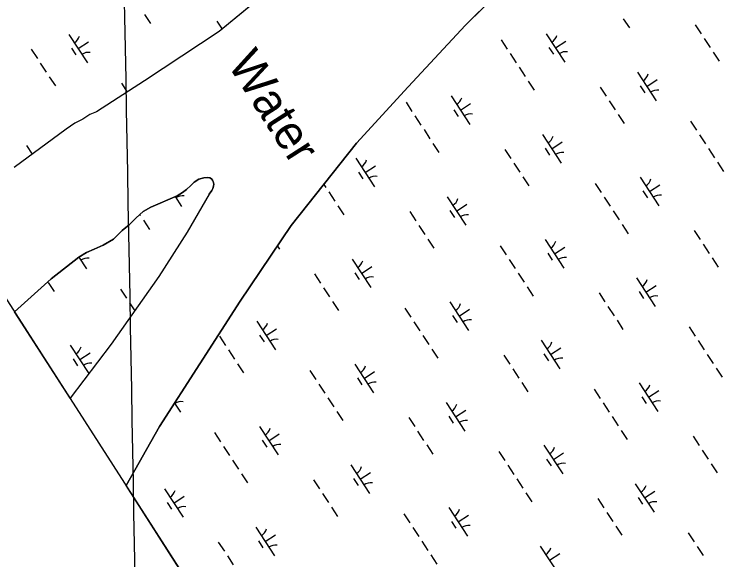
# Model space of a CAD drawing. Extents: x 3945642 to 3966284, y 206476 to 228921.
# Drawn here: x 3951439 to 3952485, y 218632 to 219430 of the extents above; entities that cross this region are included whole.
import ezdxf

# ---------------------------------------------------------------- set-up
doc = ezdxf.new("R2010")
doc.units = 0
for name, color, linetype in [('V-GRID-FRAM', 7, 'Continuous'), ('V-GRID-MAJR', 7, 'Continuous'), ('V-RIVR-IDEN', 7, 'Continuous'), ('V-TOPO-SHOR', 7, 'Continuous'), ('V-WETL-SWMP', 7, 'Continuous')]:
    doc.layers.add(name, color=color, linetype=linetype)

msp = doc.modelspace()

# ---------------------------------------------------------------- linework, layer by layer
at = {"layer": 'V-GRID-FRAM'}
msp.add_lwpolyline([(3956475, 226502.1), (3964764.2, 213849), (3957669.1, 209282.6), (3949512, 222000.5), (3956475, 226502.1)], dxfattribs=at)
at = {"layer": 'V-GRID-MAJR'}
msp.add_spline([(3951631.4, 217770), (3951621.8, 218291.8), (3951515.4, 224098.9)], degree=3, dxfattribs=at)
at = {"layer": 'V-TOPO-SHOR'}
for points in [[(3952516.2, 219647.7), (3952413.8, 219612.1), (3952398.5, 219606.6), (3952388.4, 219602.3), (3952380.9, 219598.4), (3952373.2, 219594.9), (3952364, 219592), (3952354.9, 219589.5), (3952248.7, 219535.6), (3952209.6, 219512.6), (3952194.3, 219504), (3952183.8, 219494.8), (3952174.7, 219486.4), (3952166.1, 219479.3), (3952152.1, 219466.9), (3952098.8, 219414.1), (3952015.1, 219324), (3951939.5, 219241.4), (3951844.2, 219121.1), (3951769.5, 219010.5), (3951651.5, 218826.9), (3951602.7, 218740.9)], [(3951841.5, 219489.7), (3951738.6, 219404.8), (3951629.8, 219332.5), (3951559.3, 219287.4), (3951549.8, 219283.3), (3951539.6, 219276.8), (3951527.8, 219270.7), (3951515.1, 219262.1), (3951438.9, 219205.9)], [(3951724, 219167), (3951728.2, 219172.4), (3951729.5, 219175.1), (3951730.4, 219178.5), (3951730.8, 219181.8), (3951730.1, 219185.5), (3951729.3, 219187.2), (3951727.5, 219189.3), (3951725.3, 219190.6), (3951721.6, 219191.4), (3951716.4, 219190.8), (3951709.1, 219188.7), (3951702.3, 219184.4), (3951697.2, 219179.7), (3951691.2, 219173.8), (3951685.2, 219169.3), (3951677.3, 219164.7), (3951639.1, 219148.1), (3951627.7, 219141.4), (3951617.7, 219132.5), (3951607.2, 219122.2), (3951597.2, 219113.6), (3951584.1, 219101.3), (3951569, 219092.2), (3951556.1, 219086.7), (3951544.8, 219081.4), (3951533.8, 219074.6), (3951493.4, 219043.1), (3951439.7, 218995)], [(3951724, 219167), (3951692.2, 219111.1), (3951650.5, 219046.4), (3951581, 218947.6), (3951520.8, 218868.5)]]:
    msp.add_lwpolyline(points, dxfattribs=at)
at = {"layer": 'V-WETL-SWMP'}
for p, q in [((3951841.5, 219489.7), (3951738.6, 219404.8)), ((3952098.8, 219414.1), (3952152.1, 219466.9)), ((3951629.6, 219429.9), (3951638.4, 219416.5)), ((3952329.7, 219423.5), (3952338.5, 219410.1)), ((3951735.3, 219420.2), (3951743, 219408.5)), ((3952015.1, 219324), (3952098.8, 219414.1)), ((3952434.9, 219414.8), (3952443.7, 219401.4)), ((3951738.6, 219404.8), (3951629.8, 219332.5)), ((3952216.9, 219401.7), (3952244.3, 219359.9)), ((3951518.9, 219400.7), (3951546.3, 219358.9)), ((3952151.1, 219392.6), (3952159.9, 219379.2)), ((3952230.6, 219380.8), (3952245.6, 219390.7)), ((3952448.1, 219394.7), (3952456.8, 219381.4)), ((3951522.8, 219380.6), (3951529.4, 219370.6)), ((3951532.6, 219379.8), (3951547.6, 219389.7)), ((3952220.8, 219381.6), (3952227.4, 219371.6)), ((3951464.2, 219378.9), (3951473, 219365.5)), ((3952164.2, 219372.5), (3952173, 219359.1)), ((3952461.2, 219374.7), (3952470, 219361.3)), ((3951477.3, 219358.8), (3951486.1, 219345.4)), ((3952177.4, 219352.5), (3952186.2, 219339.1)), ((3951490.5, 219338.7), (3951499.3, 219325.4)), ((3952350.5, 219345.5), (3952377.9, 219303.7)), ((3951629.8, 219332.5), (3951559.3, 219287.4)), ((3951596.2, 219329.1), (3951604.5, 219316.3)), ((3952190.6, 219332.4), (3952199.3, 219319)), ((3952364.2, 219324.6), (3952379.2, 219334.5)), ((3951939.5, 219241.4), (3952015.1, 219324)), ((3952295.8, 219323.7), (3952304.6, 219310.3)), ((3952354.4, 219325.4), (3952361, 219315.3)), ((3952077.8, 219310.6), (3952105.2, 219268.8)), ((3952012, 219301.5), (3952020.7, 219288.1)), ((3952091.5, 219289.7), (3952106.5, 219299.5)), ((3952308.9, 219303.6), (3952317.7, 219290.2)), ((3951559.3, 219287.4), (3951549.8, 219283.3)), ((3952081.7, 219290.5), (3952088.3, 219280.4)), ((3951539.6, 219276.8), (3951527.8, 219270.6)), ((3951549.8, 219283.3), (3951539.6, 219276.8)), ((3952025.1, 219281.4), (3952033.9, 219268)), ((3952322.1, 219283.5), (3952330.9, 219270.1)), ((3951527.8, 219270.6), (3951515.1, 219262.1)), ((3952427.8, 219273.8), (3952436.5, 219260.5)), ((3951515.1, 219262.1), (3951438.9, 219205.9)), ((3952038.3, 219261.3), (3952047, 219247.9)), ((3952211.3, 219254.4), (3952238.7, 219212.5)), ((3952440.9, 219253.8), (3952449.7, 219240.4)), ((3951457, 219237.9), (3951465.3, 219225.3)), ((3951844.2, 219121.1), (3951939.5, 219241.4)), ((3952051.4, 219241.2), (3952060.2, 219227.8)), ((3952215.3, 219234.2), (3952221.9, 219224.2)), ((3952225, 219233.4), (3952240.1, 219243.3)), ((3952454.1, 219233.7), (3952462.8, 219220.3)), ((3952156.6, 219232.5), (3952165.4, 219219.1)), ((3951938.6, 219219.4), (3951966, 219177.6)), ((3952467.2, 219213.6), (3952476, 219200.2)), ((3951952.3, 219198.5), (3951967.4, 219208.4)), ((3952169.8, 219212.4), (3952178.6, 219199.1)), ((3951942.6, 219199.3), (3951949.1, 219189.3)), ((3952182.9, 219192.4), (3952191.7, 219179)), ((3952354.4, 219191.8), (3952381.8, 219150)), ((3951697.2, 219179.7), (3951702.3, 219184.4)), ((3951702.3, 219184.4), (3951709.1, 219188.7)), ((3951709.1, 219188.7), (3951716.4, 219190.8)), ((3951716.4, 219190.8), (3951721.6, 219191.4)), ((3951721.6, 219191.4), (3951725.3, 219190.6)), ((3951725.3, 219190.6), (3951727.5, 219189.3)), ((3951727.5, 219189.3), (3951729.3, 219187.2)), ((3951729.3, 219187.2), (3951730.1, 219185.5)), ((3951730.1, 219185.5), (3951730.8, 219181.8)), ((3951730.8, 219181.8), (3951730.4, 219178.5)), ((3951891.8, 219181.3), (3951894.7, 219176.8)), ((3952288.6, 219182.7), (3952297.4, 219169.3)), ((3951685.2, 219169.3), (3951691.2, 219173.8)), ((3951691.2, 219173.8), (3951697.2, 219179.7)), ((3951728.2, 219172.4), (3951724, 219167)), ((3951729.5, 219175.1), (3951728.2, 219172.4)), ((3951730.4, 219178.5), (3951729.5, 219175.1)), ((3952358.4, 219171.7), (3952364.9, 219161.7)), ((3952368.1, 219170.9), (3952383.2, 219180.8)), ((3951639.1, 219148.1), (3951677.3, 219164.7)), ((3951674.3, 219163.4), (3951683.8, 219149)), ((3951677.3, 219164.7), (3951685.2, 219169.3)), ((3951724, 219167), (3951692.2, 219111.1)), ((3951899.1, 219170.2), (3951907.9, 219156.8)), ((3952072.2, 219163.2), (3952099.6, 219121.4)), ((3952301.8, 219162.6), (3952310.5, 219149.2)), ((3951912.3, 219150.1), (3951921, 219136.7)), ((3952085.9, 219142.3), (3952101, 219152.2)), ((3951617.7, 219132.5), (3951627.7, 219141.4)), ((3951627.7, 219141.4), (3951639.1, 219148.1)), ((3952017.5, 219141.4), (3952026.3, 219128)), ((3952076.2, 219143.1), (3952082.7, 219133)), ((3952314.9, 219142.5), (3952323.7, 219129.2)), ((3951607.2, 219122.2), (3951617.7, 219132.5)), ((3951622.7, 219136.9), (3951623.6, 219135.5)), ((3951597.2, 219113.6), (3951607.2, 219122.2)), ((3951628, 219128.8), (3951636.8, 219115.4)), ((3951769.5, 219010.5), (3951844.2, 219121.1)), ((3952030.7, 219121.3), (3952039.4, 219107.9)), ((3952328.1, 219122.5), (3952336.8, 219109.1)), ((3951584.1, 219101.3), (3951597.2, 219113.6)), ((3951692.2, 219111.1), (3951650.5, 219046.4)), ((3952433.3, 219113.7), (3952442.1, 219100.4)), ((3951569, 219092.2), (3951584.1, 219101.3)), ((3952043.8, 219101.2), (3952052.6, 219087.8)), ((3952215.3, 219100.7), (3952242.7, 219058.8)), ((3951556.1, 219086.7), (3951569, 219092.2)), ((3951823.9, 219091), (3951826.9, 219086.5)), ((3952149.5, 219091.5), (3952158.2, 219078.2)), ((3952229, 219079.7), (3952244, 219089.6)), ((3952446.5, 219093.7), (3952455.2, 219080.3)), ((3951533.8, 219074.6), (3951544.8, 219081.4)), ((3951544.8, 219081.4), (3951556.1, 219086.7)), ((3952219.2, 219080.5), (3952225.8, 219070.5)), ((3951493.4, 219043.1), (3951533.8, 219074.6)), ((3951527.6, 219069.8), (3951527.8, 219069.5)), ((3951533.7, 219074.6), (3951544.7, 219057.8)), ((3951933.1, 219072), (3951960.5, 219030.2)), ((3952162.6, 219071.5), (3952171.4, 219058.1)), ((3952459.6, 219073.6), (3952468.4, 219060.2)), ((3951946.8, 219051.1), (3951961.8, 219061)), ((3951650.5, 219046.4), (3951581, 218947.6)), ((3951878.4, 219050.2), (3951887.1, 219036.8)), ((3951937, 219051.9), (3951943.6, 219041.9)), ((3952175.8, 219051.4), (3952184.5, 219038)), ((3951439.7, 218995), (3951493.4, 219043.1)), ((3951488.9, 219037.7), (3951497.6, 219024.3)), ((3952348.9, 219044.4), (3952376.3, 219002.6)), ((3951594.5, 219028), (3951603.3, 219014.6)), ((3951891.5, 219030.1), (3951900.3, 219016.8)), ((3952188.9, 219031.3), (3952197.7, 219017.9)), ((3952352.8, 219024.3), (3952359.4, 219014.3)), ((3952362.6, 219023.5), (3952377.6, 219033.4)), ((3952294.2, 219022.6), (3952302.9, 219009.2)), ((3951607.7, 219007.9), (3951615.3, 218996.3)), ((3951651.5, 218826.9), (3951769.5, 219010.5)), ((3951904.7, 219010.1), (3951913.4, 218996.7)), ((3952076.1, 219009.5), (3952103.5, 218967.7)), ((3951520.8, 218868.5), (3951439.7, 218995)), ((3952010.3, 219000.4), (3952019.1, 218987)), ((3952089.8, 218988.6), (3952104.9, 218998.5)), ((3952307.3, 219002.5), (3952316.1, 218989.1)), ((3952080.1, 218989.4), (3952086.7, 218979.3)), ((3951793.9, 218980.9), (3951821.3, 218939.1)), ((3952023.5, 218980.3), (3952032.3, 218966.9)), ((3952320.5, 218982.4), (3952329.2, 218969.1)), ((3952426.1, 218972.8), (3952434.9, 218959.4)), ((3951807.6, 218960), (3951822.7, 218969.8)), ((3951739.2, 218959.1), (3951748, 218945.7)), ((3951797.9, 218960.8), (3951804.5, 218950.7)), ((3952036.6, 218960.2), (3952045.4, 218946.8)), ((3952209.7, 218953.3), (3952237.1, 218911.5)), ((3952439.3, 218952.7), (3952448.1, 218939.3)), ((3951581, 218947.6), (3951520.8, 218868.5)), ((3951521.2, 218946), (3951548.3, 218904.6)), ((3952223.4, 218932.4), (3952238.5, 218942.2)), ((3951534.9, 218925.1), (3951550, 218934.9)), ((3951752.4, 218939), (3951761.1, 218925.6)), ((3952049.8, 218940.2), (3952058.6, 218926.8)), ((3952155, 218931.4), (3952163.8, 218918.1)), ((3952213.7, 218933.2), (3952220.3, 218923.1)), ((3952452.4, 218932.6), (3952461.2, 218919.2)), ((3951525.2, 218925.9), (3951531.7, 218915.8)), ((3951765.5, 218918.9), (3951774.3, 218905.5)), ((3951937, 218918.4), (3951964.4, 218876.5)), ((3952168.2, 218911.4), (3952176.9, 218898)), ((3952465.6, 218912.5), (3952474.4, 218899.2)), ((3951871.2, 218909.2), (3951880, 218895.8)), ((3951950.7, 218897.4), (3951965.8, 218907.3)), ((3951884.4, 218889.2), (3951893.1, 218875.8)), ((3951941, 218898.2), (3951947.5, 218888.2)), ((3952181.3, 218891.3), (3952190.1, 218877.9)), ((3952352.8, 218890.7), (3952380.2, 218848.9)), ((3952287, 218881.6), (3952295.8, 218868.2)), ((3952366.5, 218869.8), (3952381.5, 218879.7)), ((3951897.5, 218869.1), (3951906.3, 218855.7)), ((3952356.7, 218870.6), (3952363.3, 218860.6)), ((3951673.5, 218861.2), (3951682.2, 218847.9)), ((3952070.6, 218862.1), (3952098, 218820.3)), ((3952300.1, 218861.5), (3952308.9, 218848.2)), ((3951910.7, 218849), (3951919.4, 218835.6)), ((3952084.3, 218841.2), (3952099.3, 218851.1)), ((3952015.9, 218840.3), (3952024.7, 218826.9)), ((3952074.5, 218842), (3952081.1, 218832)), ((3952313.3, 218841.5), (3952322.1, 218828.1)), ((3951602.7, 218740.9), (3951651.5, 218826.9)), ((3951797.9, 218827.2), (3951825.3, 218785.4)), ((3951732.1, 218818.1), (3951740.8, 218804.7)), ((3951811.6, 218806.3), (3951826.6, 218816.2)), ((3952029, 218820.2), (3952037.8, 218806.8)), ((3952326.5, 218821.4), (3952335.2, 218808)), ((3951801.8, 218807.1), (3951808.4, 218797)), ((3952431.7, 218812.7), (3952440.5, 218799.3)), ((3951745.2, 218798), (3951754, 218784.6)), ((3952042.2, 218800.1), (3952051, 218786.8)), ((3952213.7, 218799.6), (3952241.1, 218757.8)), ((3952147.9, 218790.5), (3952156.6, 218777.1)), ((3952227.4, 218778.7), (3952242.4, 218788.5)), ((3952444.8, 218792.6), (3952453.6, 218779.2)), ((3951758.4, 218777.9), (3951767.1, 218764.5)), ((3952217.6, 218779.5), (3952224.2, 218769.4)), ((3951931.4, 218771), (3951958.8, 218729.2)), ((3952161, 218770.4), (3952169.8, 218757)), ((3952458, 218772.5), (3952466.8, 218759.1)), ((3951771.5, 218757.9), (3951780.3, 218744.5)), ((3951945.1, 218750.1), (3951960.2, 218759.9)), ((3951876.7, 218749.1), (3951885.5, 218735.8)), ((3951935.4, 218750.9), (3951942, 218740.8)), ((3952174.2, 218750.3), (3952182.9, 218736.9)), ((3952347.2, 218743.4), (3952374.6, 218701.5)), ((3952266.6, 217705.7), (3951602.7, 218740.9)), ((3951658.7, 218736.1), (3951686.1, 218694.2)), ((3952360.9, 218722.5), (3952376, 218732.3)), ((3951672.4, 218715.1), (3951687.5, 218725)), ((3951889.9, 218729.1), (3951898.7, 218715.7)), ((3952187.3, 218730.2), (3952196.1, 218716.9)), ((3952292.5, 218721.5), (3952301.3, 218708.1)), ((3952351.2, 218723.2), (3952357.8, 218713.2)), ((3951662.7, 218715.9), (3951669.3, 218705.9)), ((3951903.1, 218709), (3951911.8, 218695.6)), ((3952074.5, 218708.4), (3952101.9, 218666.6)), ((3952305.7, 218701.4), (3952314.5, 218688.1)), ((3952008.7, 218699.3), (3952017.5, 218685.9)), ((3952088.2, 218687.5), (3952103.3, 218697.4)), ((3951792.3, 218679.8), (3951819.7, 218638)), ((3952021.9, 218679.2), (3952030.6, 218665.9)), ((3952078.5, 218688.3), (3952085, 218678.3)), ((3952318.8, 218681.4), (3952327.6, 218668)), ((3951806, 218658.9), (3951821.1, 218668.8)), ((3952424.5, 218671.7), (3952433.3, 218658.3)), ((3951796.3, 218659.7), (3951802.8, 218649.7)), ((3952035, 218659.2), (3952043.8, 218645.8)), ((3951737.6, 218658), (3951746.4, 218644.6)), ((3952208.1, 218652.2), (3952235.5, 218610.4)), ((3952437.7, 218651.6), (3952446.4, 218638.2)), ((3951750.8, 218637.9), (3951759.5, 218624.5)), ((3952048.2, 218639.1), (3952056.9, 218625.7)), ((3952221.8, 218631.3), (3952236.9, 218641.2))]:
    msp.add_line(p, q, dxfattribs=at)
for centre, start, end in [((3951517.6, 219403.1), 302.4575, 344.0011), ((3952215.7, 219404.1), 302.4575, 344.0011), ((3951547.9, 219356.8), 82.4574, 124.0011), ((3952245.9, 219357.8), 82.4574, 124.0011), ((3952349.2, 219347.8), 302.4575, 344.0011), ((3952379.5, 219301.6), 82.4574, 124.0011), ((3952076.5, 219312.9), 302.4575, 344.0011), ((3952106.8, 219266.7), 82.4574, 124.0011), ((3952210.1, 219256.7), 302.4575, 344.0011), ((3952240.4, 219210.5), 82.4574, 124.0011), ((3951937.4, 219221.8), 302.4575, 344.0011), ((3951967.6, 219175.5), 82.4574, 124.0011), ((3952353.2, 219194.1), 302.4575, 344.0011), ((3951685.4, 219146.9), 82.4574, 124.0011), ((3952071, 219165.5), 302.4575, 344.0011), ((3952383.4, 219147.9), 82.4574, 124.0011), ((3952101.2, 219119.3), 82.4574, 124.0011), ((3952214, 219103), 302.4575, 344.0011), ((3951546.3, 219055.8), 82.4574, 124.0011), ((3951931.8, 219074.4), 302.4575, 344.0011), ((3952244.3, 219056.8), 82.4574, 124.0011), ((3951962.1, 219028.2), 82.4574, 124.0011), ((3952347.6, 219046.8), 302.4575, 344.0011), ((3952377.9, 219000.5), 82.4574, 124.0011), ((3952074.9, 219011.8), 302.4575, 344.0011), ((3952105.2, 218965.6), 82.4574, 124.0011), ((3951792.7, 218983.2), 302.4575, 344.0011), ((3951823, 218937), 82.4574, 124.0011), ((3951520, 218948.3), 302.4575, 344.0011), ((3952208.5, 218955.6), 302.4575, 344.0011), ((3952238.8, 218909.4), 82.4574, 124.0011), ((3951550.2, 218902.1), 82.4574, 124.0011), ((3951935.8, 218920.7), 302.4575, 344.0011), ((3951966, 218874.5), 82.4574, 124.0011), ((3952351.6, 218893.1), 302.4575, 344.0011), ((3951683.8, 218845.9), 82.4574, 124.0011), ((3952069.3, 218864.5), 302.4575, 344.0011), ((3952381.8, 218846.9), 82.4574, 124.0011), ((3952099.6, 218818.2), 82.4574, 124.0011), ((3951796.6, 218829.5), 302.4575, 344.0011), ((3951826.9, 218783.3), 82.4574, 124.0011), ((3952212.4, 218801.9), 302.4575, 344.0011), ((3952242.7, 218755.7), 82.4574, 124.0011), ((3951930.2, 218773.3), 302.4575, 344.0011), ((3951960.5, 218727.1), 82.4574, 124.0011), ((3951657.5, 218738.4), 302.4575, 344.0011), ((3952346, 218745.7), 302.4575, 344.0011), ((3952376.3, 218699.5), 82.4574, 124.0011), ((3951687.8, 218692.2), 82.4574, 124.0011), ((3952073.3, 218710.8), 302.4575, 344.0011), ((3952103.5, 218664.6), 82.4574, 124.0011), ((3951791.1, 218682.2), 302.4575, 344.0011), ((3951821.3, 218635.9), 82.4574, 124.0011), ((3952206.9, 218654.5), 302.4575, 344.0011)]:
    msp.add_arc(centre, 17.6, start, end, dxfattribs=at)

# ---------------------------------------------------------------- texts
at = {"layer": 'V-RIVR-IDEN'}
msp.add_text('Water', height=50, rotation=302.6757, dxfattribs=at).set_placement((3951750.1, 219357.2))

doc.saveas('drawing.dxf')
